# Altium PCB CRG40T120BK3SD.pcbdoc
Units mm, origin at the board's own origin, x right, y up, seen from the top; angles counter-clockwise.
Board outline 28.56 x 18.32 mm, 2 copper layers (Top Layer, Bottom Layer), stack 0 mm thick; 1 components, 0 nets, 3 pads, 0 vias.
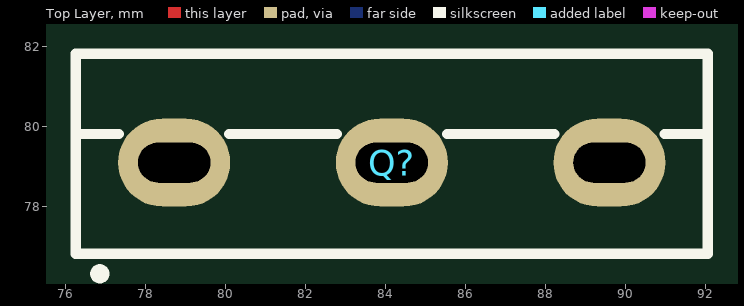
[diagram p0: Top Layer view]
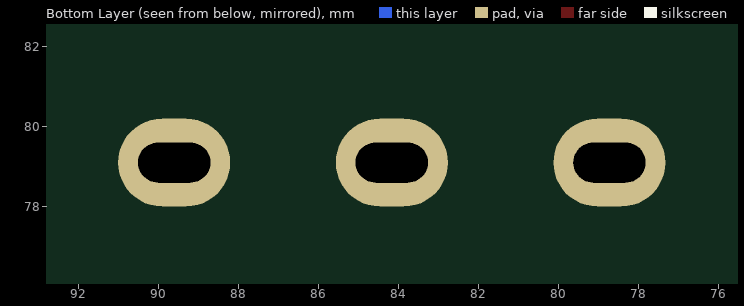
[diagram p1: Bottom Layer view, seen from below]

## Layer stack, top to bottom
Top Layer: signal copper (thickness not stored)
Bottom Layer: signal copper (thickness not stored)

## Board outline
98.41,69.85 69.85,69.85 69.85,88.17 98.41,88.17

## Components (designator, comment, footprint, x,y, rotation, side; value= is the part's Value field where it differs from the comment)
Q? "CRG40T120BK3SD" TO-247-3_L15.8-W5.0-P5.44-L 84.16,79.1 r0 top

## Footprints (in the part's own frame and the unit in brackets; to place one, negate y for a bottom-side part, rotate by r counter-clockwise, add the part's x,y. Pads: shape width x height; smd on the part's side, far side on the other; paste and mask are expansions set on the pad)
TO-247-3_L15.8-W5.0-P5.44-L [mm]
  oval 2.8x2.2 hole 1 slot 1.8 at 0 deg paste+0 mask+0.05: 1(-5.44,0) 2(0,0) 3(5.44,0)
  silkscreen extent -7.9,-2.9 7.9,2.72

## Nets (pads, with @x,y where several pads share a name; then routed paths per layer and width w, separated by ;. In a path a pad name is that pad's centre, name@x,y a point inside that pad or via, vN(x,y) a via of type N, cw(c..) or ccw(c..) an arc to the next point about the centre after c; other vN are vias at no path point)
pads on no net: Q?.1 Q?.2 Q?.3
